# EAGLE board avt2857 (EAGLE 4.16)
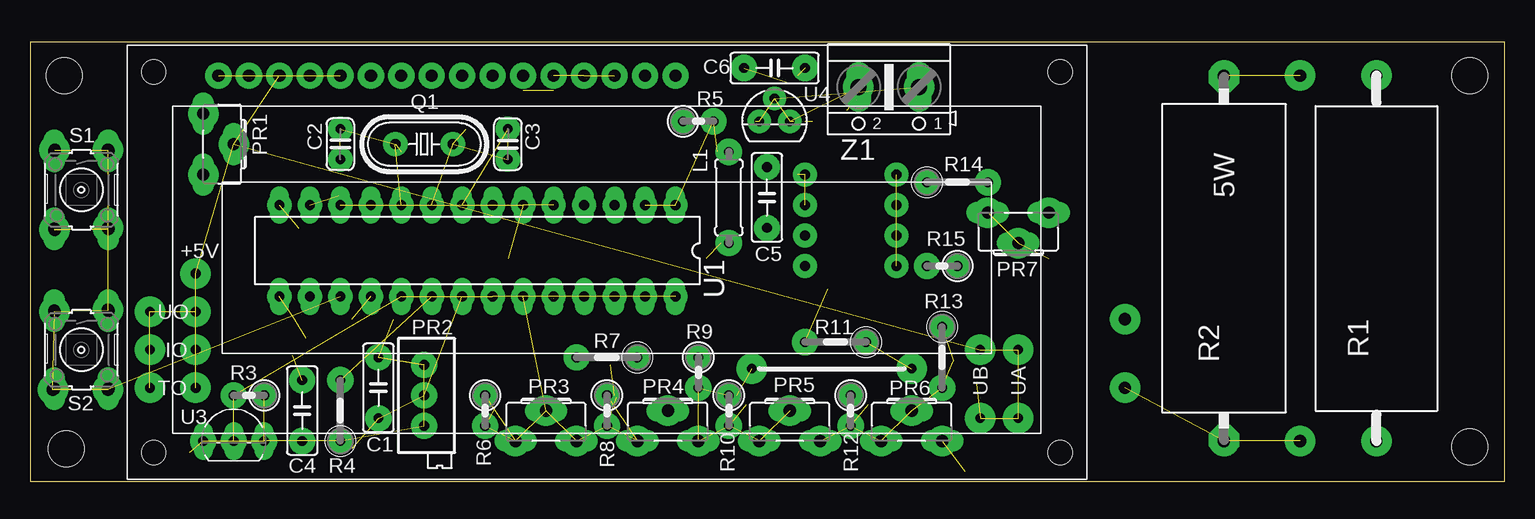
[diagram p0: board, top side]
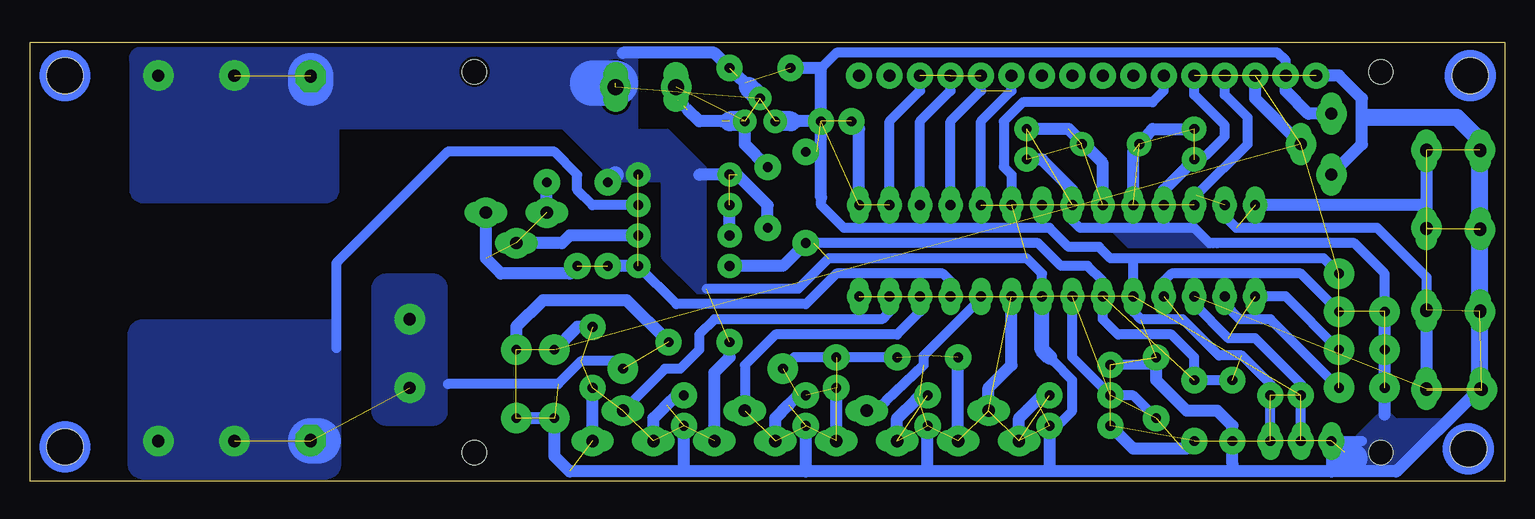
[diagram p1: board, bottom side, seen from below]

Size 122.92 x 36.61 mm. Coordinates in mm from the lower left corner, seen from the top.
Outline: 0,0 122.92,0 122.92,36.61 0,36.61 0,0
Copper layers (1*16): Top 0.035mm / dielectric 1.5mm / Bottom 0.035mm
Design rules "default": minimum track width 10mil, minimum drill 24mil, track to track 8mil, track to pad 8mil, pad to pad 8mil, via to via 8mil, smd to smd 8mil, copper to edge 1mil, drill to drill 8mil, minimum pad ring 15mil, minimum via ring 8mil, stop-mask expansion 4mil, vias tented up to drill 0mil, thermal gap 10mil
Holes 3 mm at 2.85,33.82 3.01,2.71 120.01,2.87 120.01,33.82

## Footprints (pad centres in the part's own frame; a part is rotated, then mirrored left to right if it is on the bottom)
C050-025X075 = drill 0.813 octagon: 1 -2.54,0; 2 2.54,0
C025-024X044 = drill 0.813 octagon: 1 -1.27,0; 2 1.27,0
LCD = drill 1.016 pad 1.676 round: 1 -33.02,15.875; 2 -30.48,15.875; 3 -27.94,15.875; 4 -25.4,15.875; 5 -22.86,15.875; 6 -20.32,15.875; 7 -17.78,15.875; 8 -15.24,15.875; 9 -12.7,15.875; 10 -10.16,15.875; 11 -7.62,15.875; 12 -5.08,15.875; 13 -2.54,15.875; 14 0,15.875; 15 2.54,15.875; 16 5.08,15.875 | hole 2: -38.417,16.192; -38.417,-15.557; 37.148,16.192; 37.148,-15.557
0207/7 = drill 0.813 octagon: 1 -3.81,0; 2 3.81,0
CA6H = drill 1.016 long: A -2.54,0; E 2.54,0; S 0,2.54
RTRIMT93XA = drill 0.61 round: 1 0,-2.54; 2 0,0; 3 0,2.54
HC49U-V = drill 0.813 round: 1 -2.413,0; 2 2.413,0
KH208-8 = drill 1.016 pad 2.54 octagon: 1 -13.875,0; 2 16.415,0
0207/2V = drill 0.813 octagon: 1 -1.27,0; 2 1.27,0
0207/5V = drill 0.813 octagon: 1 -2.54,0; 2 2.54,0
B3F-10XX = drill 1.016 long: 1 -3.251,2.261; 2 3.251,2.261; 3 -3.251,-2.261; 4 3.251,-2.261
DIL28-3 = drill 0.813 long: 1 -16.51,-3.81; 2 -13.97,-3.81; 3 -11.43,-3.81; 4 -8.89,-3.81; 5 -6.35,-3.81; 6 -3.81,-3.81; 7 -1.27,-3.81; 8 1.27,-3.81; 9 3.81,-3.81; 10 6.35,-3.81; 11 8.89,-3.81; 12 11.43,-3.81; 13 13.97,-3.81; 14 16.51,-3.81; 15 16.51,3.81; 16 13.97,3.81; 17 11.43,3.81; 18 8.89,3.81; 19 6.35,3.81; 20 3.81,3.81; 21 1.27,3.81; 22 -1.27,3.81; 23 -3.81,3.81; 24 -6.35,3.81; 25 -8.89,3.81; 26 -11.43,3.81; 27 -13.97,3.81; 28 -16.51,3.81
TO92-EBC = drill 0.813 long: DQ 0,-1.27; GND -2.54,-1.27; VDD 2.54,-1.27
TO92 = drill 0.813 octagon: 1 -1.27,0; 2 0,1.905; 3 1.27,0
AK500/2 = drill 1.321 long: 1 -2.515,0; 2 2.515,0

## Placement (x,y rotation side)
C1  [C050-025X075]  29.04,7.79 90 top
C2  [C025-024X044]  25.87,28.11 90 top
C3  [C025-024X044]  39.84,28.11 270 top
C4  [C050-025X075]  22.7,5.88 90 top
C5  [C050-025X075]  61.43,23.66 270 top
C6  [C050-025X075]  62.07,34.46 0 top
E$8  [LCD]  48.73,17.95 0 top
L1  [0207/7]  58.26,23.66 270 top
PR1  10k  [CA6H]  14.44,28.11 270 top
PR2  [RTRIMT93XA]  32.86,7.16 180 top
PR3  10k  [CA6H]  43.02,3.35 0 top
PR4  10k  [CA6H]  53.18,3.35 0 top
PR5  10k  [CA6H]  63.34,3.35 0 top
PR6  10k  [CA6H]  73.5,3.35 0 top
PR7  10k  [CA6H]  82.39,22.39 180 top
Q1  [HC49U-V]  32.86,28.11 0 top
R2  [KH208-8]  99.53,17.31 90 top
R3  [0207/2V]  18.25,7.16 180 top
R4  [0207/5V]  25.87,5.88 90 top
R5  [0207/2V]  55.72,30.01 0 top
R6  [0207/2V]  37.94,5.88 270 top
R7  [0207/5V]  48.1,10.33 180 top
R8  [0207/2V]  48.1,5.88 270 top
R9  [0207/2V]  55.72,9.06 270 top
R10  [0207/2V]  58.26,5.88 270 top
R11  [0207/5V]  67.14,11.6 180 top
R12  [0207/2V]  68.42,5.88 270 top
R13  [0207/5V]  76.03,10.33 270 top
R14  [0207/5V]  77.31,24.93 0 top
R15  [0207/2V]  76.03,17.95 180 top
S1  S  [B3F-10XX]  4.28,24.3 270 top
S2  S  [B3F-10XX]  4.28,10.96 270 top
U1  MEGA8  [DIL28-3]  37.3,19.22 180 top
U3  DS18B20  [TO92-EBC]  16.98,4.62 0 top
U4  78L05Z  [TO92]  62.07,30.01 0 top
Z1  [AK500/2]  71.59,32.87 180 top

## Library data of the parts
C1-C6 L1 PR2 R3-R15 = rcl
E$8 R2 S1 S2 U1 U3 = 00-my_lib
PR1 PR3-PR7 = pot
Q1 = crystal
U4 = linear
Z1 = con-ptr500

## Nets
N$10: U1.2
S$1: C3.2 Q1.2 U1.9
S$2: C2.2 Q1.1 U1.10
S$3: C3.1 U1.8
S$4: R5.2 U1.1
S$5: C1.1 PR2.2 U1.21
S$6: C1.2 PR2.1
S$7: R4.2 U1.20
S$8: S1.2 S1.4
S$9: S2.2 S2.4 U1.17
S$10: R3.2 U1.19 U3.DQ
S$11: R3.1 U3.VDD
S$13: PR3.A R6.1
S$14: PR4.A R8.1
S$15: PR3.S U1.23
S$16: PR2.3 R4.1
S$18: PR4.E R9.2
S$19: PR7.A
S$20: PR7.E
S$22: PR7.S
S$28: C5.2
S$29: E$8.1 E$8.5
S$30: E$8.3 PR1.S
S$32: U4.2 Z1.1
S$33: U4.3 Z1.2
S$88: E$8.13 R14.1

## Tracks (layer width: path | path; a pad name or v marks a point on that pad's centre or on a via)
+  (via drill 1.02 pad 2.54)  (1 unrouted)
  Bottom 0.813: 72.23,23.03 76.03,23.03 77.31,24.3 77.31,25.57 79.21,27.47 88.1,27.47 97.39,18.18 97.39,11.09
  Bottom 3.81: 99.53,3.35 98.89,3.35
  other vias: 105.88,3.35 112.23,3.35
  pour Bottom (no thermals): 98.26,0.17 arc-90 96.99,1.44 96.99,13.51 113.5,13.51 arc-90 114.77,12.24 114.77,1.44 arc-90 113.5,0.17
S$1  (2 unrouted)
S$2  (2 unrouted)
S$3  (1 unrouted)
S$4  (1 unrouted)
S$5  (2 unrouted)
S$6  (1 unrouted)
S$7  (1 unrouted)
S$8  (1 unrouted)
S$9  (2 unrouted)
S$10  (2 unrouted)
S$11  (1 unrouted)
S$13  (1 unrouted)
S$14  (1 unrouted)
S$15  (1 unrouted)
S$16  (1 unrouted)
S$17  (via drill 0.81 pad 2.54)
  other vias: 14.44,25.57
S$18  (1 unrouted)
S$21
  Bottom 1.422: 11.58,30.33 3.96,30.33 2.06,28.43 2.06,21.12
S$24  (via drill 0.81 pad 1.93, 0.81 pad 2.18, 0.81 pad 2.54)  (7 unrouted)
  Bottom 1.016: 68.42,31.28 68.89,31.76 69.05,31.92 v69.05,32.87 | 68.1,30.97 67.14,30.01 65.24,30.01 | v63.34,30.01 63.34,28.11 v61.43,26.2
  Bottom 1.676: 63.65,30.01 64.61,30.01 | 59.53,30.01 60.48,30.01
  other vias: 62.07,31.92 60.8,30.01
S$25  (via drill 0.81 pad 2.03, 0.81 pad 2.18)  (4 unrouted)
  Bottom 0.813: 48.73,32.55 48.73,32.87 | 48.73,32.55 v48.73,33.82 | 48.73,32.55 51.27,30.01 v51.27,23.03
  Bottom 1.016: 57.3,27.47 v58.26,27.47 | v54.45,30.01 53.81,29.38 v53.81,23.03
  other vias: 46.19,33.82 56.98,30.01
S$29  (1 unrouted)
S$30  (1 unrouted)
S$32  (1 unrouted)
S$33  (1 unrouted)
S$36  (via drill 0.81 pad 2.18)
  other vias: 15.71,33.82
S$37  (via drill 0.81 pad 2.18)
  other vias: 18.25,33.82
S$38  (via drill 0.81 pad 2.18)
  other vias: 20.79,33.82
S$39  (via drill 0.81 pad 2.18)
  other vias: 25.87,33.82
S$40  (via drill 0.81 pad 2.18)
  other vias: 23.33,33.82
S$41  (via drill 0.81 pad 2.18)
  other vias: 28.41,33.82
S$42  (via drill 0.81 pad 2.18)
  other vias: 30.95,33.82
S$43  (via drill 0.81 pad 2.18)
  other vias: 41.11,33.82
S$44  (via drill 0.81 pad 2.18)
  other vias: 43.65,33.82
S$47  (via drill 0.81 pad 2.18)
  other vias: 51.27,33.82
S$48  (via drill 0.81 pad 2.18)
  other vias: 53.81,33.82
S$49  (via drill 0.81 pad 2.18)
  other vias: 33.49,33.82
S$50  (via drill 0.81 pad 2.18)
  other vias: 38.57,33.82
S$51  (via drill 0.81 pad 2.18)
  other vias: 36.03,33.82
S$52  (via drill 0.81 pad 2.54)
  other vias: 14.44,30.65
S$53  (via drill 0.81 pad 2.54)  (11 unrouted)
  other vias: 16.98,28.11 13.8,7.79 13.8,10.96 9.99,10.96 9.99,7.79 82.39,5.25 79.21,5.25 82.39,10.96 79.21,10.96 9.99,14.14 13.8,14.14 13.8,17.31
S$57  (via drill 1.02 pad 2.54)  (7 unrouted)
  other vias: 6.5,27.63 2.06,27.63 2.06,20.97 6.5,21.12 6.5,14.3 6.5,7.63 1.9,7.63 2.06,14.14
S$58
  Bottom 0.813: 23.33,33.82 23.33,32.24 21.43,30.33 21.43,28.11 25.55,23.98
S$59
  Bottom 0.813: 25.87,33.82 25.87,32.24 23.33,29.7 23.33,28.74 24.92,27.16 25.55,27.16 26.19,26.52
S$62
  Bottom 1.016: 26.5,26.2 28.41,24.3 28.41,23.03
S$63
  Bottom 0.813: 28.41,33.82 28.41,32.55 29.36,31.6 40.16,31.6 41.75,30.01 41.75,26.2 41.11,25.57 41.11,23.98
S$68
  Bottom 0.813: 18.25,34.3 18.25,35.09 18.88,35.73 55.72,35.73 56.67,34.78
S$69
  Bottom 1.016: 59.53,34.46 56.98,34.46 56.98,29.06
S$70
  Bottom 1.016: 56.98,23.66 56.98,30.33
S$72
  Bottom 0.813: 56.98,23.35 56.98,23.03 55.08,21.12 37.94,21.12 36.35,19.54 33.81,19.54 32.86,18.58 15.07,18.58 13.8,17.31
S$73
  Bottom 0.813: 38.57,21.44 38.57,23.03
S$76
  Bottom 1.016: 6.5,23.03 20.79,23.03
S$77
  Bottom 1.016: 6.5,21.12 6.5,27.63
S$78
  Bottom 1.016: 28.41,21.44 28.41,23.03
S$81
  Bottom 1.016: 39.84,26.84 38.57,26.84 36.03,24.3 36.03,23.03
S$82
  Bottom 0.813: 30.95,15.41 30.95,18.27
S$83
  Bottom 0.813: 33.49,15.41 33.49,16.68 34.76,17.95 36.98,17.95 38.89,19.85 57.3,19.85
S$87
  Bottom 0.813: 46.19,15.41 46.19,16.68 46.83,17.31 55.72,17.31 58.26,14.78 69.05,14.78 72.23,17.95
S$88  (via drill 0.81 pad 2.03, 0.81 pad 2.18, 0.81 pad 2.54, 1.02 pad 2.54)  (81 unrouted)
  Bottom 0.813: 6.5,14.14 6.5,17 10.63,21.12 22.38,21.12 23.33,22.08 v23.33,23.03 | v48.73,23.03 48.73,30.01 46.19,32.55 E$8.13 | 25.71,23.82 25.87,23.66 v25.87,23.03 | v46.19,23.03 46.19,30.01 43.65,32.55 43.65,33.82 | 41.11,33.82 41.11,32.55 43.65,30.01 v43.65,23.03 | 66.51,16.04 58.89,16.04 56.35,18.58 39.84,18.58 38.57,17.31 v38.57,15.41 | v41.11,23.03 41.11,23.66 | v43.65,15.41 43.65,15.25 48.41,10.49 48.41,9.7 51.59,6.68 52.38,5.88 v53.18,5.88 | v73.5,9.38 74.13,10.01 76.99,10.01 78.89,8.11 88.1,8.11 | 11.9,3.35 v14.44,3.35 14.44,0.8 | v22.7,8.43 v25.87,8.43 | v30.95,15.41 30.95,14.14 30.31,13.51 26.82,13.51 23.81,10.49 21.9,10.49 19.52,8.11 v19.52,7.16 v19.52,3.35
  Bottom 1.016: v64.61,17.95 60.16,17.95 v58.26,19.85 57.62,19.85 | v37.94,7.16 38.57,7.16 39.05,6.68 | v68.42,7.16 69.05,7.16 69.84,6.36 | v48.1,7.16 48.73,7.16 48.89,7 | 26.82,2.71 26.5,2.71 v25.87,3.35 | v58.26,7.16 58.89,7.16 59.68,6.36 | 79.21,5.25 79.21,2.07 77.94,0.8 58.26,0.8 | 58.26,0.8 v58.26,4.62 | 58.26,0.8 14.44,0.8 9.04,0.8 2.22,7.63 | v64.61,20.49 v64.61,23.03 | 67.14,25.57 63.97,25.57 61.43,23.03 v61.43,21.12 | v79.84,22.39 v79.84,24.93 | v84.92,22.39 84.92,18.58 83.66,17.31 77.94,17.31 v77.31,17.95 | v72.23,17.95 v74.77,17.95 | 73.5,35.73 65.88,35.73 63.97,33.82 63.34,33.19 | 9.99,5.57 9.99,10.81 | v25.87,29.38 29.36,29.38 30.95,27.47 v30.95,23.03 | v39.84,29.38 36.35,29.38 33.49,26.52 v33.49,23.03
  Bottom 1.422: R14.1 74.13,25.57
  Bottom 2.54: 12.69,1.92 12.85,1.92 13.33,2.39
  Bottom 3.81: 74.13,33.19 76.03,33.19 | v99.53,33.82 99.53,33.19
  other vias: 20.79,23.03 25.87,26.84 28.41,23.03 39.84,26.84 64.61,11.6 36.03,23.03 38.57,23.03 28.41,15.41 33.49,15.41 53.81,15.41 37.94,4.62 51.27,15.41 36.03,15.41 48.73,15.41 40.48,3.35 43.02,5.88 46.19,15.41 41.11,15.41 45.55,3.35 50.64,3.35 48.1,4.62 45.55,10.33 50.64,10.33 63.34,5.88 65.88,3.35 68.42,4.62 32.86,4.62 32.86,7.16 70.95,3.35 69.69,11.6 73.5,5.88 32.86,9.7 29.04,5.25 29.04,10.33 76.03,12.87 76.03,7.79 55.72,10.33 55.72,7.79 16.98,7.16 60.16,9.38 22.7,3.35 76.03,3.35 55.72,3.35 60.8,3.35 16.98,3.35 64.61,25.57 82.39,19.85 72.23,25.57 72.23,23.03 72.23,20.49 64.61,34.46 59.53,34.46 74.77,24.93 91.28,7.79 91.28,13.51 74.13,32.87 105.88,33.82 112.23,33.82 99.53,3.35 35.24,28.11 30.47,28.11
  pour Bottom (no thermals): 89.37,17.31 93.18,17.31 arc-90 94.45,16.04 94.45,5.88 arc-90 93.18,4.62 89.37,4.62 arc-90 88.1,5.88 88.1,16.04 arc-90
  pour Bottom (isolate 0.254, no thermals): 66.51,24.93 66.51,15.63 67.37,15.63 67.37,15.64 70.14,18.41 arc45 70.32,18.84 70.32,24.93
  pour Bottom (isolate 0.254, no thermals): 66.51,24.3 66.51,26.2 69.69,29.38 72.23,29.38 72.23,36.21 113.98,36.21 arc-90 114.61,34.94 114.61,24.3 arc-90 113.5,23.19 98.26,23.19 arc-90 97.15,24.3 97.15,29.38 78.58,29.38 76.03,26.84
  pour Bottom (no thermals): 76.03,26.84 74.13,24.93 68.42,24.93 70.32,26.84
  pour Bottom (no thermals): 4.6,5.25 9.04,5.25 9.68,5.88 10.31,5.88 12.54,3.66 12.54,1.12 12.22,0.8 9.04,0.8
S$89
  Bottom 0.813: 28.41,15.41 28.41,16.68 27.77,17.31 16.98,17.31 13.8,14.14
S$90
  Bottom 0.813: 20.79,15.41 18.25,15.41 13.8,10.96
S$91  (via drill 0.81 pad 2.03)  (2 unrouted)
  Bottom 0.813: 13.8,7.79 19.52,13.51 22.06,13.51 23.33,14.78 v23.33,15.41 | 16.98,8.11 20.79,11.92 23.01,11.92 25.87,14.78 v25.87,15.41
  other vias: 20.79,15.41
S$94
  Bottom 0.813: 33.49,15.41 33.49,13.51 32.22,12.24 27.77,12.24 25.87,10.33 25.87,8.43
S$95
  Bottom 0.813: 29.04,5.25 30.95,7.16 32.86,7.16
S$96
  Bottom 0.813: 32.86,7.16 36.03,10.33 36.03,15.41
S$97
  Bottom 0.813: 37.62,10.01 36.03,8.43 36.03,5.88 37.3,4.62 37.94,4.62
  Bottom 1.016: 37.94,4.62 37.94,1.44
S$98
  Bottom 0.813: 60.16,9.38 59.21,10.33 55.72,10.33
S$99
  Bottom 0.813: 50.64,10.33 55.72,10.33
S$101
  Bottom 1.016: 18.25,33.98 18.25,32.55 16.34,30.65 14.44,30.65
S$102
  Bottom 1.016: 20.79,33.82 20.79,31.92 16.98,28.11
S$103
  Bottom 1.016: 15.71,33.82 13.8,33.82 11.9,31.92 11.9,28.11 14.44,25.57
S$104
  Bottom 1.016: 6.5,7.63 6.5,14.3
S$105
  Bottom 1.016: 9.99,10.96 9.99,14.14
S$107
  Bottom 1.016: 26.98,2.71 30.95,2.71 32.86,4.62
S$108
  Bottom 1.016: 22.7,3.03 22.7,4.62 23.96,5.88 26.5,5.88 29.04,8.43 29.04,10.33
S$109
  Bottom 1.016: 40.48,3.5 40.48,5.25 39.21,6.52
S$111
  Bottom 1.016: 79.21,5.25 82.39,5.25
S$112
  Bottom 1.016: 76.03,3.35 76.03,7.79
S$113
  Bottom 1.016: 70,6.2 70.95,5.25 70.95,3.35
S$114
  Bottom 1.016: 68.42,1.44 68.42,4.62
S$115
  Bottom 1.016: 64.61,11.6 64.61,10.33 65.88,9.06 65.88,3.35
S$116
  Bottom 1.016: 55.72,3.35 55.72,7.79
S$117
  Bottom 1.016: 59.68,6.36 60.8,5.25 60.8,3.35
S$118
  Bottom 1.016: 45.55,3.35 45.55,10.33
S$119
  Bottom 1.016: 49.05,6.84 50.64,5.25 50.64,3.35
S$120
  Bottom 1.016: 41.11,15.41 41.11,9.7 43.02,7.79 43.02,5.88
S$121
  Bottom 1.27: 38.57,15.25 38.57,10.96 37.94,10.33
S$122
  Bottom 1.016: 48.1,1.12 48.1,4.62
S$124
  Bottom 1.016: 22.7,1.44 22.7,3.03
S$125
  Bottom 0.813: 16.98,3.35 16.98,8.11
S$127
  Bottom 0.813: 29.2,9.7 32.86,9.7
S$128
  Bottom 0.813: 48.73,15.41 48.73,14.14 50.64,12.24 60.8,12.24 63.34,9.7 63.34,5.88
S$129
  Bottom 0.813: 51.27,15.41 51.27,14.14 51.91,13.51 65.88,13.51 67.14,12.24 67.14,10.96 68.73,9.38 70,9.38 73.5,5.88
S$130
  Bottom 1.016: 69.69,11.6 73.18,15.09 80.16,15.09 82.39,12.87 82.39,10.96
S$132
  Bottom 1.016: 82.23,19.85 78.58,19.85 77.94,20.49 72.23,20.49
S$133
  Bottom 1.016: 79.21,10.96 77.31,12.87 76.03,12.87
S$135
  Bottom 1.676: 62.38,32.24 63.02,32.87
S$138
  Bottom 1.016: 56.98,30.01 58.89,30.01
S$143
  Bottom 1.422: 2.06,13.51 2.06,20.81
S$144
  Bottom 0.813: 36.03,23.19 36.03,21.76 35.4,21.12 25.87,21.12 24.6,19.85 23.96,19.85 | 9.99,14.14 9.99,17.31 12.54,19.85 23.96,19.85 | 23.96,19.85 24.28,19.85
  pour Bottom (no thermals): 24.6,19.85 24.6,19.45 26.94,19.45 31.42,19.45 31.42,19.46 32.82,20.86 26.03,20.86 24.63,19.46
S$145
  Bottom 1.422: 2.06,7.79 2.06,12.87
(copper drawn outside any net)
  shapes: Bottom circle x4

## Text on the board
tNames: +5V | UO | IO | R1 | TO | UB | UA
